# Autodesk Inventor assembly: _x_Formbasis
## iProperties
Created: 2005-11
Part Number: _x_Formbasis
Document SubType Name: Assembly
Designer: IMA/Frank
Manufacturer: Standard
Standards Organization: Custom
Author: IMA/Frank
